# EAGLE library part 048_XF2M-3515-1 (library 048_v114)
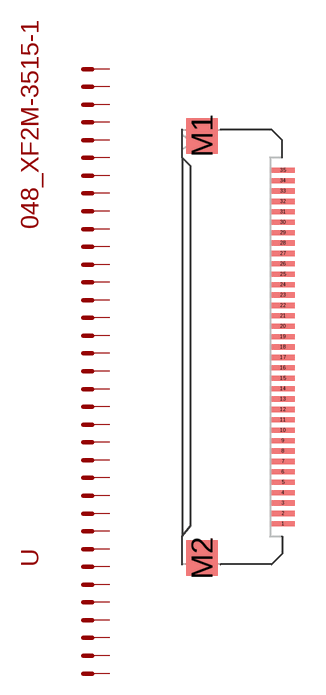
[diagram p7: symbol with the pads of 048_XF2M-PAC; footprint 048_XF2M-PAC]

Designator prefix -

## 048_XF2M-3515-1  [048_XF2M-PAC]
1  1  pas
2  2  pas
3  3  pas
4  4  pas
5  5  pas
6  6  pas
7  7  pas
8  8  pas
9  9  pas
10  10  pas
11  11  pas
12  12  pas
13  13  pas
14  14  pas
15  15  pas
16  16  pas
17  17  pas
18  18  pas
19  19  pas
20  20  pas
21  21  pas
22  22  pas
23  23  pas
24  24  pas
25  25  pas
26  26  pas
27  27  pas
28  28  pas
29  29  pas
30  30  pas
31  31  pas
32  32  pas
33  33  pas
34  34  pas
35  35  pas

## Footprint 048_XF2M-PAC (pad centres in mm)
smd 1.1 x 0.25: 1 2.54,-8.52; 2 2.54,-8.02; 3 2.54,-7.52; 4 2.54,-7.02; 5 2.54,-6.52; 6 2.54,-6.02; 7 2.54,-5.52; 8 2.54,-5.02; 9 2.54,-4.52; 10 2.54,-4.02; 11 2.54,-3.52; 12 2.54,-3.02; 13 2.54,-2.52; 14 2.54,-2.02; 15 2.54,-1.52; 16 2.54,-1.02; 17 2.54,-0.52; 18 2.54,-0.02; 19 2.54,0.48; 20 2.54,0.98; 21 2.54,1.48; 22 2.54,1.98; 23 2.54,2.48; 24 2.54,2.98; 25 2.54,3.48; 26 2.54,3.98; 27 2.54,4.48; 28 2.54,4.98; 29 2.54,5.48; 30 2.54,5.98; 31 2.54,6.48; 32 2.54,6.98; 33 2.54,7.48; 34 2.54,7.98; 35 2.54,8.48
smd 1.5 x 1.7: M1 -1.36,10.13; M2 -1.36,-10.17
